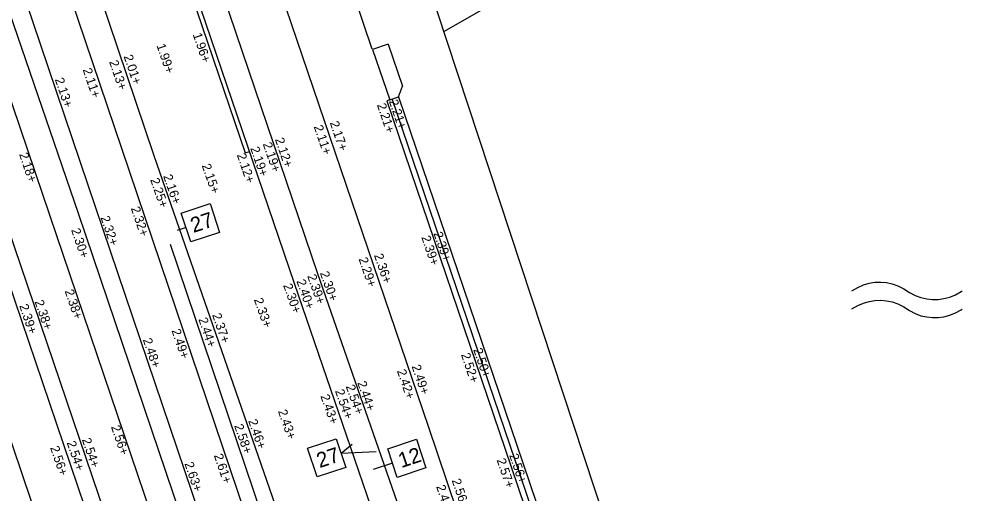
# Model space of a CAD drawing. Extents: x 122462 to 123306, y 485548 to 486417.
# Drawn here: x 122832.7 to 122864.07, y 486096.08 to 486111.75 of the extents above; entities that cross this region are included whole.
import ezdxf

# ---------------------------------------------------------------- set-up
doc = ezdxf.new("R2010")
doc.units = 0
for name, color, linetype in [('B nummers', 7, 'Continuous'), ('B-WE-AL-WERKGRENS-G', 7, 'Continuous'), ('B-WE-IE-TERREINAFSCHEIDING_KUNSTMATIG_HEKWERK-G', 7, 'Continuous'), ('B-WE-OG-HOOGTEPUNT-S', 7, 'Continuous'), ('B-WE-OG-TOPOGRAFIE_MUUR-G', 7, 'Continuous'), ('B-WE-OG-TOPOGRAFIE_RAILS-G', 7, 'Continuous'), ('B-WE-VH-KANTOPSLUITING_TROTTOIRBAND_180 200-G', 7, 'Continuous'), ('B-WE-VW-MARKERING_LANGS_STREEP_DOORGETROKKEN_010-G', 7, 'Continuous'), ('Level 16', 7, 'Continuous'), ('Level 55', 7, 'Continuous'), ('V materiaalscheiding algemeen', 7, 'Continuous'), ('V Rails', 7, 'Continuous'), ('V RWS-band 115-225x250 mm specie', 7, 'Continuous'), ('V trottoirband 180-200x250 mm specie', 7, 'Continuous'), ('V zaaglijn', 7, 'Continuous')]:
    doc.layers.add(name, color=color, linetype=linetype)

msp = doc.modelspace()

# ---------------------------------------------------------------- linework, layer by layer
at = {"layer": 'B nummers'}
for p, q in [((122838.217, 486104.858), (122837.927, 486104.763)), ((122843.334, 486097.4), (122843.698, 486097.697)), ((122843.334, 486097.4), (122844.495, 486097.457)), ((122845.034, 486097.072), (122844.391, 486096.86))]:
    msp.add_line(p, q, dxfattribs=at)
for points in [[(122838.06, 486105.333), (122839.01, 486105.647), (122839.323, 486104.697), (122838.374, 486104.384)], [(122842.227, 486097.561), (122843.177, 486097.875), (122843.49, 486096.925), (122842.541, 486096.612)], [(122844.877, 486097.547), (122845.827, 486097.86), (122846.14, 486096.911), (122845.191, 486096.597)]]:
    msp.add_lwpolyline(points, close=True, dxfattribs=at)
at = {"layer": 'B-WE-AL-WERKGRENS-G'}
msp.add_lwpolyline([(122857.632, 486078.279), (122830.484, 486160.606), (122900.937, 486183.81), (122887.855, 486222.555), (122665.445, 486149.273), (122678.196, 486110.449), (122807.072, 486152.895), (122835.324, 486068.154)], dxfattribs=at)
at = {"layer": 'B-WE-IE-TERREINAFSCHEIDING_KUNSTMATIG_HEKWERK-G'}
msp.add_lwpolyline([(122853.708, 486083.572), (122845.028, 486109.114)], dxfattribs=at)
at = {"layer": 'B-WE-OG-TOPOGRAFIE_MUUR-G'}
msp.add_line((122841.519, 486119.16), (122844.35, 486110.759), dxfattribs=at)
for points in [[(122844.894, 486110.919), (122844.373, 486110.74), (122844.944, 486109.076), (122845.227, 486109.178), (122845.362, 486109.528)], [(122844.894, 486110.919), (122845.362, 486109.528)], [(122844.944, 486109.076), (122844.85, 486109.044), (122848.957, 486096.949), (122853.545, 486083.39), (122853.637, 486083.421)], [(122845.227, 486109.178), (122849.336, 486097.077), (122853.924, 486083.518)]]:
    msp.add_lwpolyline(points, dxfattribs=at)
at = {"layer": 'B-WE-OG-TOPOGRAFIE_RAILS-G'}
for p, q in [((122836.339, 486106.728), (122844.174, 486083.54)), ((122834.974, 486106.268), (122842.81, 486083.078)), ((122833.474, 486105.961), (122841.189, 486083.208)), ((122832.11, 486105.5), (122839.825, 486082.745))]:
    msp.add_line(p, q, dxfattribs=at)
at = {"layer": 'B-WE-VH-KANTOPSLUITING_TROTTOIRBAND_180 200-G'}
for points in [[(122839.772, 486076.05), (122830.973, 486102.107), (122827.132, 486113.429)], [(122831.584, 486105.321), (122832.323, 486103.149), (122836.246, 486091.538), (122841.344, 486076.501)]]:
    msp.add_lwpolyline(points, dxfattribs=at)
at = {"layer": 'B-WE-VW-MARKERING_LANGS_STREEP_DOORGETROKKEN_010-G'}
msp.add_lwpolyline([(122842.379, 486082.508), (122834.669, 486105.323), (122830.244, 486118.192), (122825.281, 486132.973), (122822.384, 486141.602), (122818.71, 486152.508)], dxfattribs=at)
at = {"layer": 'Level 16'}
msp.add_lwpolyline([(122846.733, 486111.33), (122850.475, 486113.488), (122863.386, 486119.194), (122871.86, 486122.983), (122876.67, 486124.799)], dxfattribs=at)
at = {"layer": 'Level 55'}
for points in [[(122860.208, 486102.765), (122860.398, 486102.879), (122860.588, 486102.96), (122860.778, 486103.015), (122860.968, 486103.045), (122861.158, 486103.052), (122861.348, 486103.035), (122861.538, 486102.995), (122861.728, 486102.929), (122861.918, 486102.834), (122862.108, 486102.711), (122862.298, 486102.613), (122862.488, 486102.543), (122862.678, 486102.5), (122862.868, 486102.48), (122863.058, 486102.482), (122863.248, 486102.507), (122863.438, 486102.557), (122863.628, 486102.633), (122863.818, 486102.739), (122863.853, 486102.763)], [(122860.208, 486102.165), (122860.398, 486102.279), (122860.588, 486102.36), (122860.778, 486102.415), (122860.968, 486102.445), (122861.158, 486102.452), (122861.348, 486102.435), (122861.538, 486102.395), (122861.728, 486102.329), (122861.918, 486102.234), (122862.108, 486102.111), (122862.298, 486102.013), (122862.488, 486101.943), (122862.678, 486101.9), (122862.868, 486101.88), (122863.058, 486101.882), (122863.248, 486101.907), (122863.438, 486101.957), (122863.628, 486102.033), (122863.818, 486102.139), (122863.853, 486102.163)]]:
    msp.add_lwpolyline(points, dxfattribs=at)
at = {"layer": 'V materiaalscheiding algemeen'}
msp.add_lwpolyline([(122835.041, 486122.41), (122838.047, 486113.577), (122840.172, 486107.322), (122840.315, 486107.372)], dxfattribs=at)
at = {"layer": 'V Rails'}
for p, q in [((122819.673, 486156.047), (122836.339, 486106.728)), ((122818.309, 486155.586), (122834.974, 486106.268)), ((122817.744, 486152.354), (122833.474, 486105.961))]:
    msp.add_line(p, q, dxfattribs=at)
at = {"layer": 'V RWS-band 115-225x250 mm specie'}
msp.add_lwpolyline([(122832.367, 486121.446), (122837.147, 486107.234)], dxfattribs=at)
at = {"layer": 'V trottoirband 180-200x250 mm specie'}
for points in [[(122851.83, 486081.654), (122846.225, 486098.276), (122841.156, 486113.188), (122837.659, 486123.568)], [(122844.724, 486094.463), (122841.797, 486103.007), (122838.189, 486113.625), (122835.183, 486122.458)], [(122839.022, 486113.767), (122842.561, 486103.334), (122845.536, 486094.754)], [(122837.147, 486107.234), (122843.393, 486089.234)]]:
    msp.add_lwpolyline(points, dxfattribs=at)
at = {"layer": 'V zaaglijn'}
msp.add_line((122846.099, 486079.474), (122837.702, 486104.29), dxfattribs=at)

# ---------------------------------------------------------------- texts
at = {"layer": 'B nummers'}
for s, p in [('27', (122838.459, 486104.675)), ('27', (122842.626, 486096.903)), ('12', (122845.323, 486096.904))]:
    msp.add_text(s, height=0.5, rotation=18.2603, dxfattribs=at).set_placement(p)
at = {"layer": 'B-WE-OG-HOOGTEPUNT-S'}
for s, rotation, p in [('1.96+', 288.6561, (122838.435, 486111.237)), ('1.99+', 288.6561, (122837.235, 486110.878)), ('2.13+', 288.6561, (122835.672, 486110.334)), ('2.01+', 288.6561, (122836.152, 486110.512)), ('2.11+', 288.6561, (122834.799, 486110.072)), ('2.13+', 288.6561, (122833.879, 486109.753)), ('2.21+', 288.6343, (122844.911, 486109.034)), ('2.21+', 288.6343, (122844.516, 486108.91)), ('2.11+', 288.7678, (122842.43, 486108.19)), ('2.17+', 288.6343, (122842.961, 486108.319)), ('2.12+', 288.7678, (122841.148, 486107.771)), ('2.19+', 288.7678, (122840.334, 486107.475)), ('2.19+', 288.7678, (122840.746, 486107.621)), ('2.18+', 288.6561, (122832.697, 486107.28)), ('2.12+', 288.7376, (122839.89, 486107.255)), ('2.15+', 289.1368, (122838.73, 486106.907)), ('2.16+', 289.1368, (122837.457, 486106.556)), ('2.25+', 289.1368, (122837.028, 486106.437)), ('2.32+', 288.6499, (122836.388, 486105.496)), ('2.32+', 288.6499, (122835.389, 486105.188)), ('2.30+', 288.6499, (122834.415, 486104.779)), ('2.39+', 288.6343, (122846.385, 486104.662)), ('2.39+', 288.6343, (122845.983, 486104.536)), ('2.36+', 288.6343, (122844.42, 486103.942)), ('2.29+', 288.6343, (122843.911, 486103.821)), ('2.30+', 289.1368, (122842.633, 486103.353)), ('2.40+', 289.1368, (122841.857, 486103.087)), ('2.39+', 289.1368, (122842.214, 486103.254)), ('2.38+', 288.6499, (122834.204, 486102.757)), ('2.30+', 289.1368, (122841.419, 486102.949)), ('2.38+', 288.6499, (122833.211, 486102.409)), ('2.33+', 289.1368, (122840.454, 486102.474)), ('2.39+', 288.6499, (122832.703, 486102.273)), ('2.44+', 288.597, (122838.62, 486101.828)), ('2.37+', 288.597, (122839.073, 486101.971)), ('2.49+', 288.597, (122837.732, 486101.453)), ('2.48+', 288.6499, (122836.784, 486101.149)), ('2.50+', 288.6343, (122847.699, 486100.819)), ('2.52+', 288.6343, (122847.292, 486100.659)), ('2.49+', 288.6343, (122845.661, 486100.268)), ('2.42+', 288.6343, (122845.178, 486100.116)), ('2.54+', 289.1368, (122843.486, 486099.607)), ('2.44+', 289.1368, (122843.867, 486099.725)), ('2.43+', 289.1368, (122842.648, 486099.287)), ('2.54+', 289.1368, (122843.132, 486099.456)), ('2.43+', 289.1368, (122841.247, 486098.787)), ('2.58+', 289.1368, (122839.8, 486098.305)), ('2.46+', 289.1368, (122840.263, 486098.468)), ('2.56+', 288.597, (122835.734, 486098.27)), ('2.54+', 288.597, (122834.271, 486097.749)), ('2.54+', 288.597, (122834.773, 486097.85)), ('2.56+', 288.597, (122833.723, 486097.584)), ('2.63+', 288.597, (122838.159, 486097.057)), ('2.61+', 288.597, (122839.131, 486097.326)), ('2.57+', 288.6343, (122848.47, 486097.174)), ('2.56+', 288.6343, (122848.886, 486097.329)), ('2.56+', 288.6343, (122846.985, 486096.501)), ('2.49+', 288.6343, (122846.471, 486096.298))]:
    msp.add_text(s, height=0.3, rotation=rotation, dxfattribs=at).set_placement(p)

doc.saveas('drawing.dxf')
